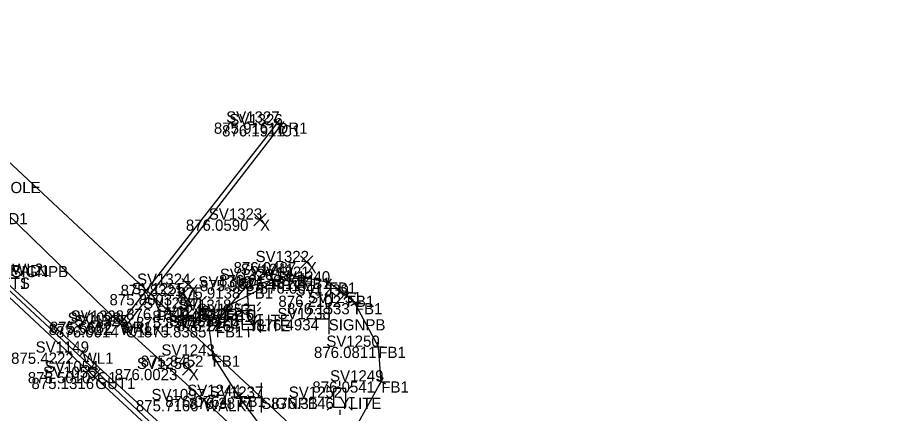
# Model space of a CAD drawing. Extents: x 1469677 to 1493262, y 375219 to 389293.
# Drawn here: x 1480224.6 to 1480318.7, y 379391.7 to 379434.1 of the extents above; entities that cross this region are included whole.
import ezdxf

# ---------------------------------------------------------------- set-up
doc = ezdxf.new("R2010")
doc.units = 0
for name, color, linetype in [('DR_X_Drive_Pipe', 7, 'Continuous'), ('DV_X_Lot_Line', 7, 'Continuous'), ('DV_X_Text', 7, 'Continuous'), ('GK_Visualization', 7, 'Continuous'), ('PNTELEV', 7, 'Continuous'), ('RD_P_Text', 7, 'Continuous'), ('RW_P_Esmt_SW', 7, 'Continuous'), ('RW_P_Esmt_U', 7, 'Continuous'), ('RW_P_Text', 7, 'Continuous'), ('rw_x_right_of_way', 7, 'Continuous'), ('SV_X_Mon_Cells_Found', 7, 'Continuous'), ('Text Border', 7, 'Continuous'), ('Text Property', 7, 'Continuous')]:
    doc.layers.add(name, color=color, linetype=linetype)

msp = doc.modelspace()

# ---------------------------------------------------------------- linework, layer by layer
at = {"layer": 'DR_X_Drive_Pipe'}
msp.add_lwpolyline([(1480172.622, 379452.503), (1480197.813, 379429.111), (1480212.628, 379415.684), (1480231.592, 379398.237), (1480249.493, 379381.828), (1480253.44, 379378.963), (1480259.284, 379374.539), (1480264.171, 379372.865), (1480269.434, 379369.248), (1480270.598, 379368.157), (1480270.755, 379365.904), (1480271.186, 379363.733), (1480285.468, 379347.959), (1480298.848, 379335.614), (1480313.013, 379322.705), (1480330.745, 379305.601), (1480344.344, 379292.312), (1480351.783, 379285.136)], dxfattribs=at)
at = {"layer": 'DV_X_Lot_Line'}
msp.add_lwpolyline([(1480355.123, 379297.828), (1480351.285, 379293.6), (1480334.098, 379309.328), (1480328.212, 379315.428), (1480328.737, 379316.329), (1480319.905, 379324.485), (1480307.606, 379335.13), (1480302.895, 379338.359), (1480281.823, 379358.406), (1480285.611, 379363.387), (1480280.441, 379367.109), (1480277.224, 379362.834), (1480260.819, 379378.019), (1480244.572, 379393.153), (1480235.613, 379401.335), (1480215.341, 379421.047), (1480197.466, 379437.463)], dxfattribs=at)
at = {"layer": 'PNTELEV'}
for p, q in [((1480252.819, 379422.558), (1480252.03, 379423.173)), ((1480252.732, 379423.259), (1480252.117, 379422.471)), ((1480252.425, 379422.865), (1480252.425, 379422.865)), ((1480252.434, 379422.886), (1480253.225, 379422.275)), ((1480252.524, 379422.185), (1480253.135, 379422.976)), ((1480252.83, 379422.58), (1480252.83, 379422.58)), ((1480253.998, 379406.467), (1480253.014, 379406.647)), ((1480253.416, 379406.065), (1480253.596, 379407.049)), ((1480253.506, 379406.557), (1480253.506, 379406.557)), ((1480255.143, 379406.747), (1480255.212, 379405.75)), ((1480251.371, 379405.881), (1480252.333, 379406.153)), ((1480251.716, 379406.498), (1480251.988, 379405.536)), ((1480251.852, 379406.017), (1480251.852, 379406.017)), ((1480254.679, 379406.214), (1480255.676, 379406.283)), ((1480255.177, 379406.249), (1480255.177, 379406.249)), ((1480258.326, 379405.451), (1480257.521, 379406.045)), ((1480257.627, 379405.346), (1480258.22, 379406.151)), ((1480257.924, 379405.748), (1480257.924, 379405.748)), ((1480248.639, 379405.544), (1480249.389, 379404.884)), ((1480248.684, 379404.839), (1480249.344, 379405.589)), ((1480249.014, 379405.214), (1480249.014, 379405.214)), ((1480259.544, 379403.933), (1480260.137, 379404.738)), ((1480260.243, 379404.039), (1480259.438, 379404.632)), ((1480259.84, 379404.335), (1480259.84, 379404.335)), ((1480260.263, 379403.298), (1480261.144, 379403.772)), ((1480260.94, 379403.095), (1480260.467, 379403.975)), ((1480246.393, 379402.979), (1480247.254, 379402.471)), ((1480246.57, 379402.295), (1480247.078, 379403.156)), ((1480260.704, 379403.535), (1480260.704, 379403.535)), ((1480236.195, 379401.244), (1480235.406, 379401.859)), ((1480236.108, 379401.946), (1480235.493, 379401.158)), ((1480245.395, 379402.291), (1480244.51, 379401.826)), ((1480245.186, 379401.616), (1480244.72, 379402.501)), ((1480244.953, 379402.058), (1480244.953, 379402.058)), ((1480246.824, 379402.725), (1480246.824, 379402.725)), ((1480235.983, 379400.998), (1480235.244, 379401.672)), ((1480235.276, 379400.966), (1480235.95, 379401.704)), ((1480235.613, 379401.335), (1480235.613, 379401.335)), ((1480235.8, 379401.552), (1480235.8, 379401.552)), ((1480235.806, 379401.366), (1480236.597, 379400.755)), ((1480235.896, 379400.665), (1480236.507, 379401.456)), ((1480236.201, 379401.061), (1480236.201, 379401.061)), ((1480245.409, 379401.313), (1480246.27, 379400.804)), ((1480245.586, 379400.628), (1480246.094, 379401.489)), ((1480245.84, 379401.059), (1480245.84, 379401.059)), ((1480263.258, 379398.363), (1480263.173, 379399.359)), ((1480231.224, 379398.576), (1480231.96, 379397.899)), ((1480231.93, 379398.605), (1480231.253, 379397.869)), ((1480231.592, 379398.237), (1480231.592, 379398.237)), ((1480245.425, 379398.415), (1480245.553, 379397.424)), ((1480262.717, 379398.819), (1480263.713, 379398.904)), ((1480263.215, 379398.861), (1480263.215, 379398.861)), ((1480245.985, 379397.984), (1480244.993, 379397.855)), ((1480245.489, 379397.92), (1480245.489, 379397.92)), ((1480232.789, 379396.49), (1480233.523, 379395.81)), ((1480233.496, 379396.517), (1480232.817, 379395.783)), ((1480232.59, 379395.879), (1480233.321, 379395.197)), ((1480233.296, 379395.904), (1480232.614, 379395.172)), ((1480232.955, 379395.538), (1480232.955, 379395.538)), ((1480233.156, 379396.15), (1480233.156, 379396.15)), ((1480263.094, 379395.392), (1480263.969, 379394.908)), ((1480263.289, 379394.713), (1480263.773, 379395.588)), ((1480263.531, 379395.15), (1480263.531, 379395.15)), ((1480244.938, 379392.812), (1480244.206, 379393.494)), ((1480244.231, 379392.787), (1480244.913, 379393.519)), ((1480248.66, 379393.878), (1480247.817, 379393.341)), ((1480247.97, 379394.031), (1480248.508, 379393.188)), ((1480248.239, 379393.61), (1480248.239, 379393.61)), ((1480244.572, 379393.153), (1480244.572, 379393.153))]:
    msp.add_line(p, q, dxfattribs=at)
at = {"layer": 'RD_P_Text'}
for points in [[(1480186.493, 379438.955), (1480206.919, 379419.855), (1480210.187, 379416.932), (1480211.433, 379415.804), (1480213.11, 379414.171), (1480218.471, 379409.217), (1480217.005, 379410.473), (1480215.222, 379412.175), (1480221.495, 379406.235), (1480232.955, 379395.538), (1480249.633, 379380.044), (1480261.648, 379368.645), (1480263.97, 379366.423), (1480266.337, 379364.241), (1480284.168, 379347.237), (1480298.679, 379333.414), (1480300.396, 379332.229), (1480315.326, 379318.045), (1480323.87, 379309.98), (1480343.087, 379291.663), (1480360.248, 379275.585)], [(1480186.975, 379439.363), (1480207.407, 379420.301), (1480210.41, 379417.305), (1480211.712, 379416.16), (1480212.774, 379415.29), (1480213.67, 379414.243), (1480215.361, 379412.945), (1480216.632, 379411.517), (1480217.745, 379410.456), (1480218.76, 379409.536), (1480221.908, 379406.565), (1480233.156, 379396.15), (1480249.934, 379380.311), (1480262.014, 379368.886), (1480262.346, 379369.254), (1480264.513, 379367.165), (1480266.627, 379365.06), (1480266.41, 379364.736), (1480284.493, 379347.537), (1480298.919, 379333.838), (1480300.736, 379332.585), (1480315.855, 379318.308), (1480323.784, 379310.749)], [(1480236.201, 379401.061), (1480252.83, 379422.58)]]:
    msp.add_lwpolyline(points, dxfattribs=at)
at = {"layer": 'RW_P_Esmt_U'}
for p, q in [((1480249.901, 379411.812), (1480251.234, 379413.147)), ((1480249.901, 379413.147), (1480251.234, 379411.812)), ((1480254.89, 379407.263), (1480256.223, 379408.598)), ((1480254.89, 379408.598), (1480256.223, 379407.263)), ((1480242.217, 379404.837), (1480243.55, 379406.172)), ((1480242.217, 379406.172), (1480243.55, 379404.837)), ((1480241.616, 379403.83), (1480242.949, 379405.165)), ((1480241.616, 379405.165), (1480242.949, 379403.83)), ((1480242.272, 379395.819), (1480243.606, 379397.154)), ((1480242.272, 379397.154), (1480243.606, 379395.819))]:
    msp.add_line(p, q, dxfattribs=at)
at = {"layer": 'RW_P_Text'}
for p, q in [((1480243.518, 379404.225), (1480243.518, 379404.756)), ((1480242.553, 379403.913), (1480242.183, 379404.288)), ((1480244.851, 379404.288), (1480244.479, 379403.913)), ((1480249.293, 379403.567), (1480249.293, 379404.099)), ((1480242.474, 379402.951), (1480241.943, 379402.951)), ((1480243.518, 379402.945), (1480243.518, 379402.945)), ((1480245.093, 379402.951), (1480244.559, 379402.951)), ((1480248.328, 379403.255), (1480247.958, 379403.63)), ((1480248.365, 379402.685), (1480247.995, 379403.06)), ((1480249.33, 379402.997), (1480249.33, 379403.529)), ((1480250.626, 379403.63), (1480250.254, 379403.255)), ((1480250.663, 379403.06), (1480250.292, 379402.685)), ((1480242.553, 379401.976), (1480242.183, 379401.601)), ((1480244.851, 379401.601), (1480244.479, 379401.976)), ((1480248.249, 379402.294), (1480247.718, 379402.294)), ((1480249.293, 379402.287), (1480249.293, 379402.287)), ((1480250.868, 379402.294), (1480250.334, 379402.294)), ((1480243.518, 379401.665), (1480243.518, 379401.133)), ((1480248.287, 379401.724), (1480247.755, 379401.724)), ((1480248.328, 379401.319), (1480247.958, 379400.944)), ((1480249.293, 379401.007), (1480249.293, 379400.475)), ((1480249.33, 379401.717), (1480249.33, 379401.717)), ((1480250.626, 379400.944), (1480250.254, 379401.319)), ((1480250.905, 379401.724), (1480250.372, 379401.724)), ((1480248.365, 379400.749), (1480247.995, 379400.374)), ((1480249.33, 379400.437), (1480249.33, 379399.905)), ((1480250.663, 379400.374), (1480250.292, 379400.749)), ((1480258.12, 379394.373), (1480257.75, 379394.748)), ((1480259.085, 379394.685), (1480259.085, 379395.217)), ((1480260.418, 379394.748), (1480260.046, 379394.373)), ((1480258.041, 379393.412), (1480257.51, 379393.412)), ((1480259.085, 379393.405), (1480259.085, 379393.405)), ((1480260.66, 379393.412), (1480260.126, 379393.412)), ((1480258.12, 379392.437), (1480257.75, 379392.062)), ((1480260.418, 379392.062), (1480260.046, 379392.437)), ((1480259.085, 379392.125), (1480259.085, 379391.593))]:
    msp.add_line(p, q, dxfattribs=at)
for points in [[(1480242.851, 379401.945), (1480244.183, 379401.945), (1480244.183, 379403.945), (1480242.851, 379403.945)], [(1480248.626, 379401.287), (1480249.958, 379401.287), (1480249.958, 379403.287), (1480248.626, 379403.287)], [(1480248.663, 379400.717), (1480249.995, 379400.717), (1480249.995, 379402.717), (1480248.663, 379402.717)], [(1480258.418, 379392.405), (1480259.75, 379392.405), (1480259.75, 379394.405), (1480258.418, 379394.405)]]:
    msp.add_lwpolyline(points, close=True, dxfattribs=at)
at = {"layer": 'rw_x_right_of_way'}
for p, q in [((1480257.907, 379403.414), (1480257.907, 379400.214)), ((1480257.907, 379401.814), (1480256.307, 379401.814)), ((1480250.68, 379395.01), (1480250.68, 379391.81)), ((1480250.68, 379393.41), (1480249.08, 379393.41))]:
    msp.add_line(p, q, dxfattribs=at)
at = {"layer": 'SV_X_Mon_Cells_Found'}
msp.add_lwpolyline([(1477206.544, 382340.781), (1479657.335, 379947.979), (1480466.338, 379191.878)], dxfattribs=at)
at = {"layer": 'Text Border'}
msp.add_lwpolyline([(1480252.425, 379422.865), (1480235.8, 379401.552)], dxfattribs=at)
at = {"layer": 'Text Property'}
msp.add_lwpolyline([(1480259.84, 379404.335), (1480257.924, 379405.748), (1480253.506, 379406.557), (1480244.953, 379402.058), (1480245.489, 379397.92), (1480248.239, 379393.61), (1480250.763, 379390.17), (1480253.969, 379388.413), (1480257.154, 379388.076), (1480260.916, 379390.426), (1480263.531, 379395.15), (1480263.215, 379398.861), (1480260.704, 379403.535)], close=True, dxfattribs=at)
msp.add_lwpolyline([(1480245.84, 379401.059), (1480246.824, 379402.725), (1480249.014, 379405.214), (1480251.852, 379406.017), (1480255.177, 379406.249)], dxfattribs=at)

# ---------------------------------------------------------------- texts
at = {"layer": 'DV_X_Text'}
for s, height, p in [('875.9161', 1.2, (1480245.63, 379421.665)), ('876.1911', 1.2, (1480246.508, 379421.38)), ('875.92', 0.06, (1480252.144, 379422.805)), ('876.19', 0.06, (1480252.572, 379422.52)), ('876.0590', 1.2, (1480242.631, 379411.28)), ('876.06', 0.06, (1480250.277, 379412.42)), ('876.0487', 1.2, (1480247.734, 379406.73)), ('876.05', 0.06, (1480255.27, 379407.87)), ('876.0129', 1.2, (1480246.174, 379405.357)), ('875.9837', 1.2, (1480244.133, 379404.817)), ('876.1014', 1.2, (1480248.319, 379405.049)), ('876.0641', 1.2, (1480250.533, 379404.548)), ('875.98', 0.06, (1480251.57, 379405.957)), ('876.10', 0.06, (1480254.914, 379406.189)), ('876.06', 0.06, (1480257.633, 379405.688)), ('875.8321', 1.2, (1480235.654, 379404.304)), ('875.9138', 1.2, (1480241.758, 379404.014)), ('875.83', 0.06, (1480242.604, 379405.444)), ('875.91', 0.06, (1480248.755, 379405.154)), ('875.8603', 1.2, (1480234.469, 379403.298)), ('875.86', 0.06, (1480241.999, 379404.438)), ('876.2102', 1.2, (1480252.528, 379403.135)), ('876.21', 0.06, (1480259.582, 379404.275)), ('876.1349', 1.2, (1480236.253, 379401.745)), ('876.1533', 1.2, (1480253.457, 379402.335)), ('876.15', 0.06, (1480260.447, 379403.475)), ('875.8572', 1.2, (1480237.3, 379400.858)), ('875.8420', 1.2, (1480239.048, 379401.525)), ('874.2428', 1.2, (1480241.621, 379401.087)), ('875.84', 0.06, (1480246.544, 379402.665)), ('875.5822', 1.2, (1480227.96, 379400.135)), ('875.6682', 1.2, (1480228.091, 379400.352)), ('876.0014', 1.2, (1480228.757, 379399.861)), ('875.58', 0.06, (1480235.332, 379401.275)), ('875.67', 0.06, (1480235.519, 379401.492)), ('876.00', 0.06, (1480235.909, 379401.001)), ('875.8385', 1.2, (1480238.14, 379399.859)), ('876.2264', 1.2, (1480241.658, 379400.517)), ('875.84', 0.06, (1480245.56, 379400.999)), ('876.23', 0.06, (1480249.05, 379401.657)), ('876.4934', 1.2, (1480250.169, 379400.614)), ('876.49', 0.06, (1480257.625, 379401.754)), ('875.4222', 1.2, (1480223.948, 379397.037)), ('875.42', 0.06, (1480231.312, 379398.177)), ('876.0811', 1.2, (1480256.326, 379397.661)), ('876.08', 0.06, (1480262.928, 379398.801)), ('875.8452', 1.2, (1480237.808, 379396.72)), ('875.85', 0.06, (1480245.209, 379397.86)), ('876.0023', 1.2, (1480235.031, 379395.287)), ('876.00', 0.06, (1480242.647, 379396.427)), ('875.5010', 1.2, (1480225.731, 379394.95)), ('875.1316', 1.2, (1480226.125, 379394.338)), ('875.13', 0.06, (1480232.699, 379395.478)), ('875.50', 0.06, (1480232.871, 379396.09)), ('876.0541', 1.2, (1480256.159, 379393.95)), ('876.05', 0.06, (1480263.244, 379395.09)), ('876.0764', 1.2, (1480240.435, 379392.41)), ('876.3877', 1.2, (1480242.98, 379392.21)), ('876.08', 0.06, (1480247.952, 379393.55)), ('876.39', 0.06, (1480250.397, 379393.35)), ('876.3146', 1.2, (1480251.754, 379392.205)), ('876.31', 0.06, (1480258.826, 379393.345)), ('875.7166', 1.2, (1480237.288, 379391.953)), ('875.72', 0.06, (1480244.293, 379393.093))]:
    msp.add_text(s, height=height, dxfattribs=at).set_placement(p)
at = {"layer": 'GK_Visualization'}
for s, p in [('DR1', (1480252.425, 379421.665)), ('C1', (1480252.83, 379421.38)), ('SGPOLE', (1480220.497, 379415.311)), ('PAD1', (1480221.522, 379411.984)), ('X', (1480250.568, 379411.28)), ('PAD1', (1480223.846, 379406.429)), ('SIGNPB', (1480223.98, 379406.314)), ('WL2', (1480224.057, 379406.57)), ('X', (1480255.557, 379406.73)), ('FB1', (1480253.506, 379405.357)), ('PAINTS', (1480220.16, 379405.079)), ('GUT1', (1480221.495, 379405.035)), ('FB1', (1480251.852, 379404.817)), ('FB1', (1480255.177, 379405.049)), ('FB1', (1480257.924, 379404.548)), ('X', (1480242.884, 379404.304)), ('FB1', (1480249.014, 379404.014)), ('X', (1480242.283, 379403.298)), ('FB1', (1480259.84, 379403.135)), ('YLITE', (1480243.518, 379401.745)), ('FB1', (1480260.704, 379402.335)), ('FB1', (1480244.953, 379400.858)), ('FB1', (1480246.824, 379401.525)), ('YLITE', (1480249.293, 379401.087)), ('WALK1', (1480235.613, 379400.135)), ('DR1', (1480235.8, 379400.352)), ('C1', (1480236.201, 379399.861)), ('FB1', (1480245.84, 379399.859)), ('YLITE', (1480249.33, 379400.517)), ('SIGNPB', (1480257.907, 379400.614)), ('WL1', (1480231.592, 379397.037)), ('FB1', (1480263.215, 379397.661)), ('FB1', (1480245.489, 379396.72)), ('X', (1480242.939, 379395.287)), ('GUT1', (1480232.955, 379394.338)), ('C1', (1480233.156, 379394.95)), ('FB1', (1480263.531, 379393.95)), ('FB1', (1480248.239, 379392.41)), ('SIGNPB', (1480250.68, 379392.21)), ('YLITE', (1480259.085, 379392.205)), ('WALK1', (1480244.572, 379391.953))]:
    msp.add_text(s, height=1.2, dxfattribs=at).set_placement(p)
at = {"layer": 'RW_P_Esmt_SW'}
for s, height, p in [('SV1327', 1.2, (1480246.945, 379422.865)), ('SV1326', 1.2, (1480247.275, 379422.58)), ('SV1327', 0.06, (1480252.151, 379422.865)), ('SV1326', 0.06, (1480252.552, 379422.58)), ('SV1323', 1.2, (1480245.089, 379412.48)), ('SV1323', 0.06, (1480250.294, 379412.48)), ('SV1322', 1.2, (1480250.087, 379407.93)), ('SV1241', 1.2, (1480248.487, 379406.557)), ('SV1322', 0.06, (1480255.284, 379407.93)), ('SV1324', 1.2, (1480237.414, 379405.504)), ('SV1320', 1.2, (1480246.269, 379406.017)), ('SV1321', 1.2, (1480250.149, 379406.249)), ('SV1240', 1.2, (1480252.35, 379405.748)), ('SV1255', 1.2, (1480236.822, 379404.498)), ('SV1319', 1.2, (1480243.979, 379405.214)), ('SV1320', 0.06, (1480251.573, 379406.017)), ('SV1321', 0.06, (1480254.926, 379406.249)), ('SV1240', 0.06, (1480257.645, 379405.748)), ('SV1324', 0.06, (1480242.611, 379405.504)), ('SV1319', 0.06, (1480248.762, 379405.214)), ('SV1239', 1.2, (1480254.351, 379404.335)), ('SV1251', 1.2, (1480255.694, 379403.535)), ('SV1254', 1.2, (1480238.067, 379402.945)), ('SV1318', 1.2, (1480241.789, 379402.725)), ('SV1255', 0.06, (1480242.01, 379404.498)), ('SV1239', 0.06, (1480259.566, 379404.335)), ('SV1242', 1.2, (1480239.493, 379402.058)), ('SV1253', 1.2, (1480243.832, 379402.287)), ('SV1316', 1.2, (1480244.229, 379401.717)), ('SV1318', 0.06, (1480246.572, 379402.725)), ('SV1238', 1.2, (1480252.418, 379401.814)), ('SV1251', 0.06, (1480260.454, 379403.535)), ('SV1098', 1.2, (1480229.992, 379401.335)), ('SV1328', 1.2, (1480230.312, 379401.552)), ('SV1325', 1.2, (1480230.722, 379401.061)), ('SV1317', 1.2, (1480240.815, 379401.059)), ('SV1238', 0.06, (1480257.633, 379401.814)), ('SV1098', 0.06, (1480235.332, 379401.335)), ('SV1328', 0.06, (1480235.526, 379401.552)), ('SV1325', 0.06, (1480235.927, 379401.061)), ('SV1317', 0.06, (1480245.589, 379401.059)), ('SV1316', 0.06, (1480249.075, 379401.717)), ('SV1250', 1.2, (1480257.651, 379398.861)), ('SV1149', 1.2, (1480226.566, 379398.237)), ('SV1243', 1.2, (1480240.019, 379397.92)), ('SV1149', 0.06, (1480231.341, 379398.237)), ('SV1250', 0.06, (1480262.937, 379398.861)), ('SV1054', 1.2, (1480227.573, 379396.15)), ('SV1256', 1.2, (1480237.403, 379396.487)), ('SV1243', 0.06, (1480245.216, 379397.92)), ('SV1055', 1.2, (1480227.362, 379395.538)), ('SV1054', 0.06, (1480232.877, 379396.15)), ('SV1256', 0.06, (1480242.662, 379396.487)), ('SV1249', 1.2, (1480258.052, 379395.15)), ('SV1055', 0.06, (1480232.675, 379395.538)), ('SV1097', 1.2, (1480238.961, 379393.153)), ('SV1244', 1.2, (1480242.779, 379393.61)), ('SV1237', 1.2, (1480245.201, 379393.41)), ('SV1252', 1.2, (1480253.634, 379393.405)), ('SV1249', 0.06, (1480263.257, 379395.15)), ('SV1244', 0.06, (1480247.966, 379393.61)), ('SV1237', 0.06, (1480250.406, 379393.41)), ('SV1252', 0.06, (1480258.812, 379393.405)), ('SV1097', 0.06, (1480244.291, 379393.153))]:
    msp.add_text(s, height=height, dxfattribs=at).set_placement(p)

doc.saveas('drawing.dxf')
